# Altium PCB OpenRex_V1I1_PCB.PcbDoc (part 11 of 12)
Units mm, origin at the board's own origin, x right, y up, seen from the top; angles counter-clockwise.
Board outline 70 x 95 mm, 10 copper layers (L1, L2, L3, L4 (PWR), L5 (PWR), L6 (PWR), L7 (PWR), L8, L9, L10), stack 1.632 mm thick; 1080 components, 708 nets, 3831 pads, 2373 vias.
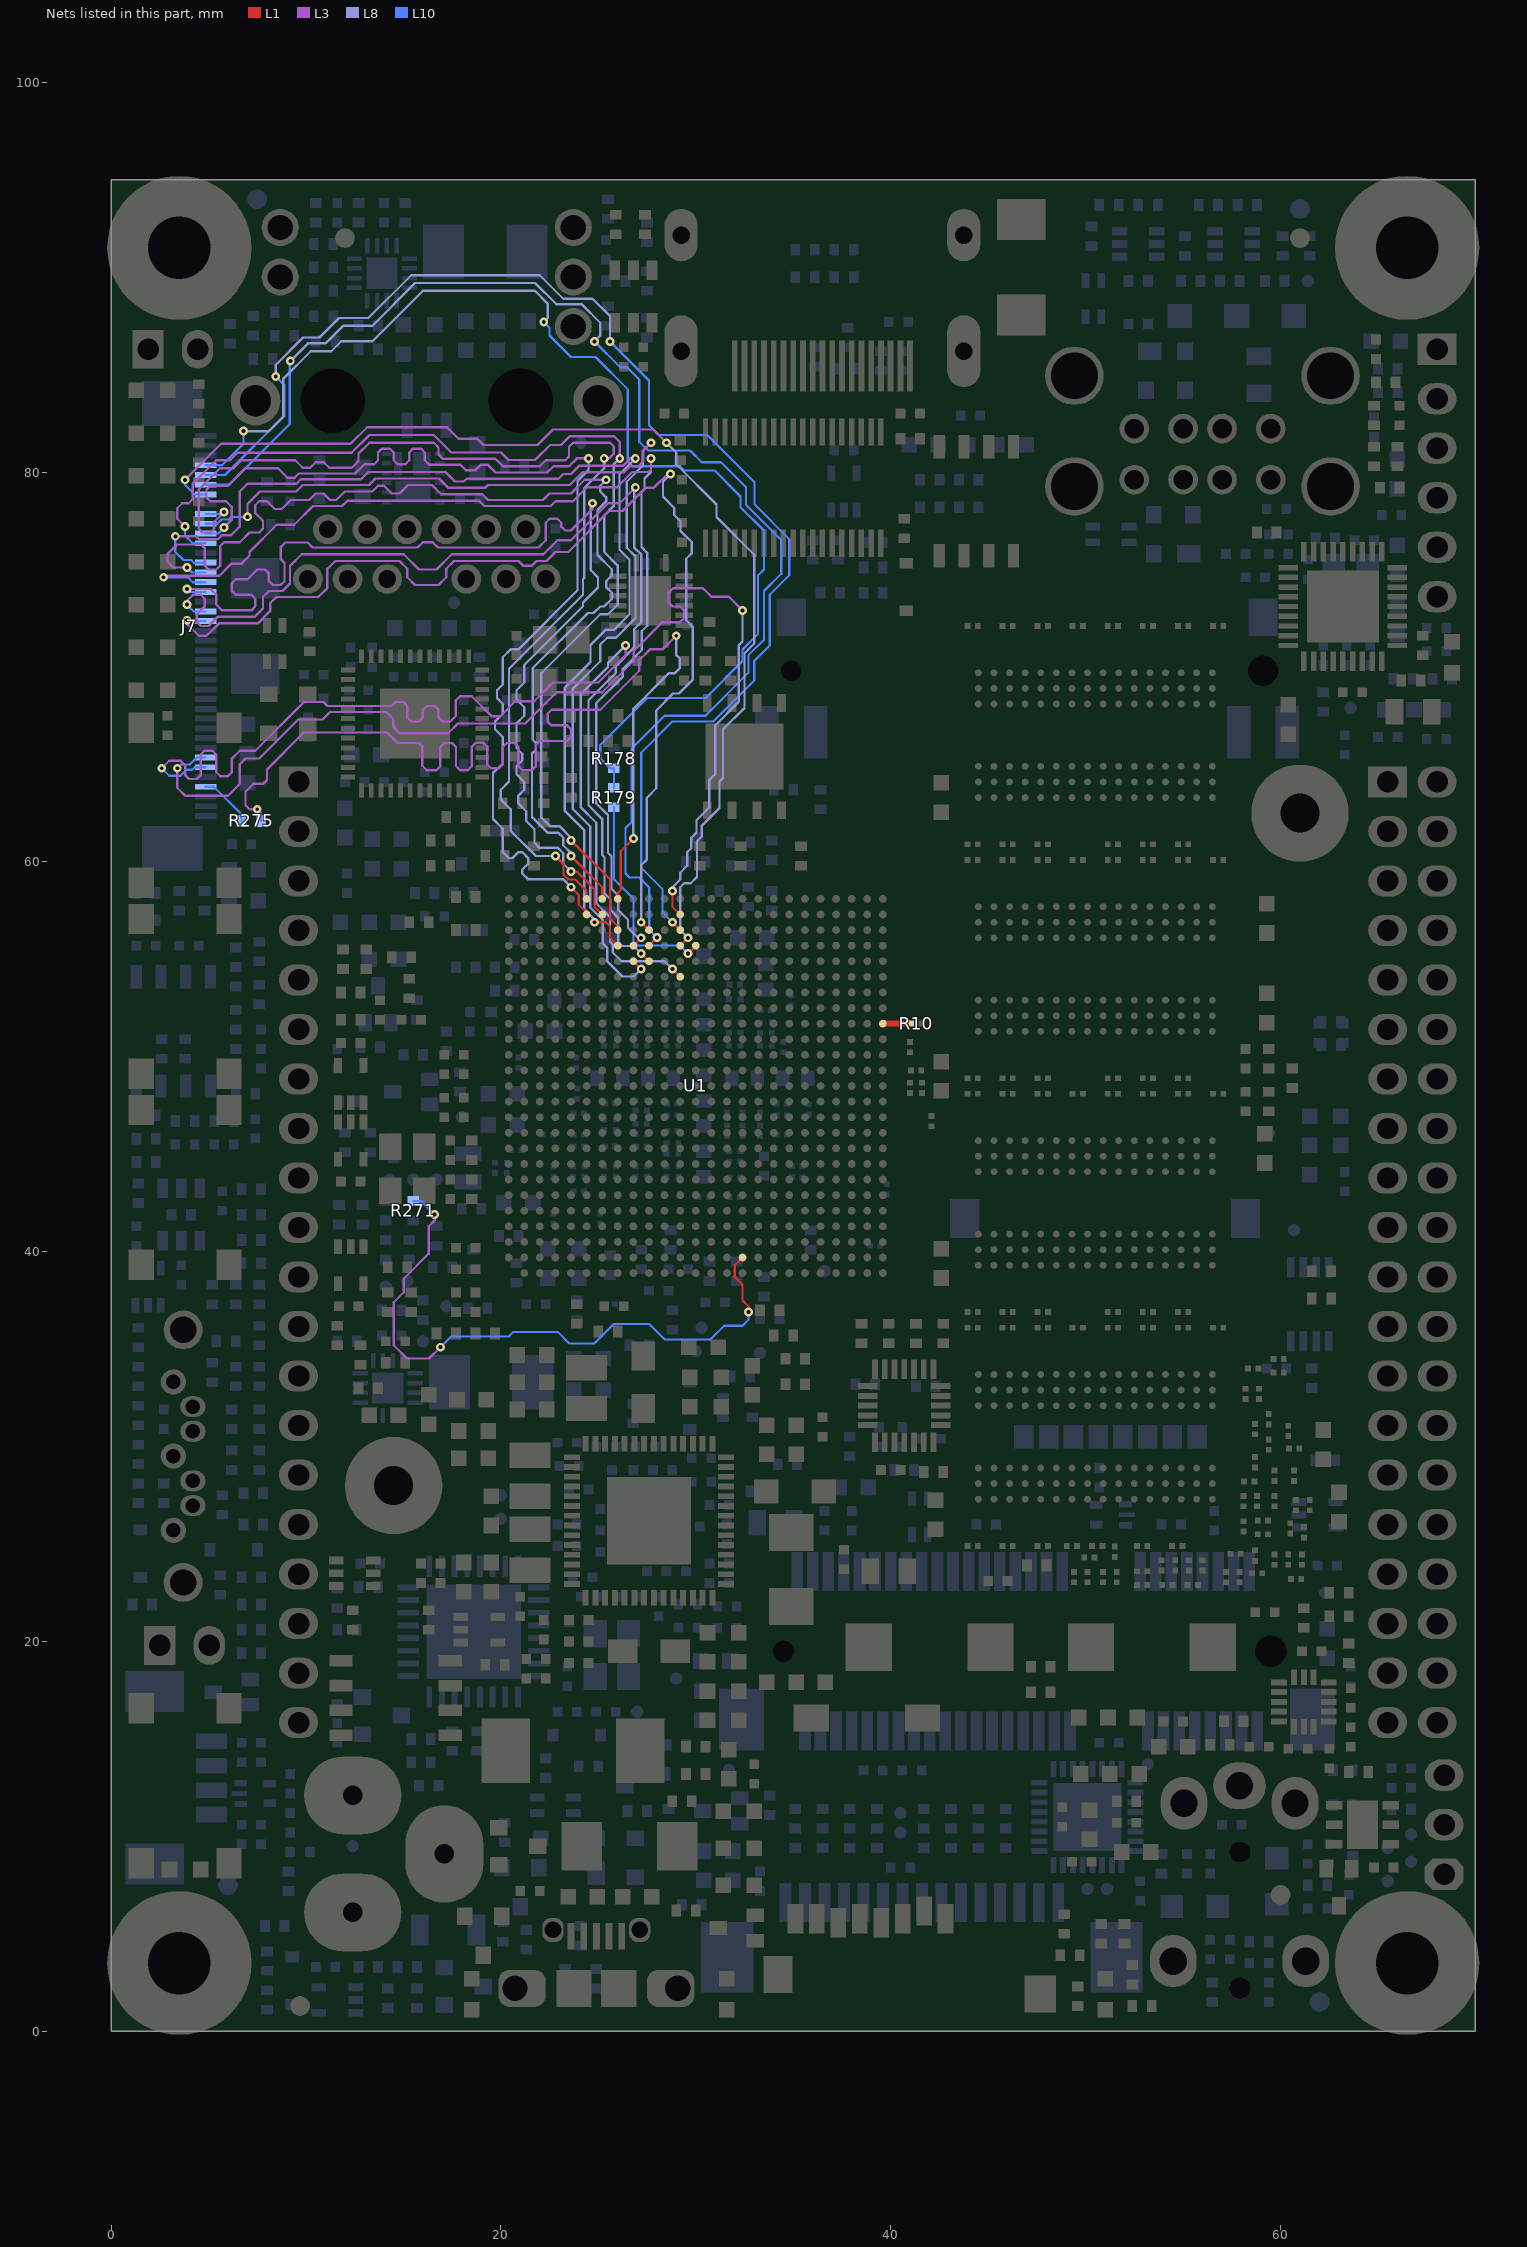
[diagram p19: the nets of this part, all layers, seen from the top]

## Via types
v1: diameter 0.45, hole 0.2, L1 to L10, tented both sides, 2369 vias
v2: diameter 1, hole 0.5, L1 to L10, tented top, 4 vias

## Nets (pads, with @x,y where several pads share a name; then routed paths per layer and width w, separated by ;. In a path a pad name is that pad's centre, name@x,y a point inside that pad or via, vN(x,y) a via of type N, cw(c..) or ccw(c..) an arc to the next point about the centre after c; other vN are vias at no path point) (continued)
VID_IN_CSI1_D10: J7.21 U1.K23 | length 58.1
  L1 w0.114: v1(27.2,56.9) U1.K23@27.6,56.5
  L3 w0.12: v1(3.9,72.4) 3.9,72.2 4.5,71.6 4.9,71.6 5.535,72.235 7.535,72.235 8.163,72.863 8.163,73.263 8.491,73.591 10.635,73.591 11.1,74.056 11.1,75.035 11.5,75.435 14.8,75.435 15.2,75.035 15.2,74.6 15.6,74.2 16.8,74.2 17.2,74.6 17.2,75.035 17.6,75.435 20.9,75.435 21.135,75.2 21.6,75.2 21.835,75.435 22.335,75.435 22.8,75.9 23.456,75.9 25.556,78 26.244,78 27.444,79.2 27.86,79.2 28.56,79.9 v1(28.7,79.9)
  L8 w0.12: v1(27.2,56.9) 27.2,59.828 27.491,60.119 27.491,63.291 27.972,63.772 27.972,67.769 28.838,68.635 29.135,68.635 29.837,69.337 29.837,72.063 29.509,72.391 29.509,75.553 29.8,75.844 29.8,76.4 29.22,76.98 29.22,77.48 28.9,77.8 28.9,78.156 28.315,78.741 28.315,79.515 v1(28.7,79.9)
  L10 w0.114: v1(3.9,72.4) 3.95,72.35 J7.21@4.85,72.35
VID_IN_CSI1_D11: J7.22 U1.K21 | length 58.1
  L1 w0.114: v1(27.2,55.3) U1.K21@27.6,54.9
  L3 w0.12: v1(3.9,73.2) 3.9,73.4 4.2,73.7 4.6,73.7 4.8,73.5 4.8,73.1 4.4,72.7 4.4,72.3 4.6,72.1 5,72.1 5.467,72.568 7.363,72.568 7.8,73.004 7.8,73.6 8.1,73.9 8.796,73.9 9.182,74.286 9.182,75.182 9.783,75.783 15.017,75.783 15.8,75 16.7,75 17.483,75.783 22.183,75.783 22.9,76.5 23.6,76.5 25.5,78.4 26.1,78.4 v1(26.9,79.2)
  L8 w0.12: v1(26.9,79.2) 26.838,79.138 26.838,76.133 27.21,75.762 27.21,72.31 26.838,71.938 26.838,70.994 25.9,70.056 25.9,69.7 24.495,68.295 24.495,62.905 25.195,62.205 25.195,60.364 25.32,60.239 25.32,58.38 25.61,58.09 25.61,57.55 26.015,57.145 26.015,55.885 26.215,55.685 26.815,55.685 v1(27.2,55.3)
  L10 w0.114: v1(3.9,73.2) 4.25,72.85 J7.22@4.85,72.85
VID_IN_CSI1_D12: J7.24 U1.G24 | length 58
  L1 w0.114: v1(23.6,59.5) 23.9,59.5 24.8,58.6 24.8,57.7 U1.G24@25.2,57.3
  L3 w0.12: v1(3.9,74) 5.1,74 5.4,73.7 5.4,73.2 5.7,72.9 7.2,72.9 7.4,73.1 7.4,73.5 7.2,73.7 6.4,73.7 6.2,73.9 6.2,74.3 6.4,74.5 7,74.5 7.5,75 7.9,75 8.1,74.8 8.1,74.4 8.3,74.2 8.7,74.2 8.9,74.4 8.9,75.326 8.715,75.511 8.715,76.159 8.941,76.385 10.088,76.385 10.342,76.131 15.731,76.131 16,76.4 16.5,76.4 16.769,76.131 21.931,76.131 22.3,76.5 22.3,77.4 22.5,77.6 22.9,77.6 23.1,77.4 23.1,77.2 23.3,77 23.6,77 24.7,78.1 v1(24.7,78.4)
  L8 w0.12: v1(23.6,59.5) 23.2,59.9 23.2,60.444 22.929,60.715 21.985,60.715 21.725,60.975 21.725,61.675 21.3,62.1 21.3,62.6 20.9,63 20.9,63.4 21.2,63.7 21.2,64.1 20.8,64.5 20.8,64.9 21.1,65.2 21.1,65.55 20.8,65.85 20.8,67.1 21.2,67.5 21.2,67.935 20.8,68.335 20.8,68.8 21.2,69.2 21.2,70.1 24.215,73.115 24.215,73.309 24.985,74.079 24.985,74.594 24.617,74.962 24.617,78.317 v1(24.7,78.4)
  L10 w0.114: v1(3.9,74) 4.05,73.85 J7.24@4.85,73.85
VID_IN_CSI1_D13: J7.25 U1.J22 | length 58.1
  L1 w0.114: U1.J22@26.8,55.7 v1(27.2,56.1)
  L3 w0.12: v1(2.7,74.6) 2.78,74.68 5.56,74.68 6.18,75.3 6.7,75.3 7.1,75.7 7.1,75.9 8.5,77.3 9.4,77.3 10.355,78.255 11.855,78.255 12.129,78.529 18.871,78.529 19.145,78.255 22.555,78.255 22.8,78.5 23.7,78.5 24.415,79.215 25.951,79.215 26.736,80 27.6,80 27.7,80.1 v1(27.7,80.7)
  L8 w0.12: v1(27.2,56.1) 27.045,56.1 26.525,56.62 26.525,57.031 26.015,57.541 26.015,58.285 25.68,58.62 25.68,60.29 25.5,60.47 25.5,62.4 24.899,63.001 24.899,68.143 26.26,69.504 26.26,69.9 27.233,70.873 27.233,71.833 27.515,72.115 27.515,72.599 27.515,75.853 27.215,76.153 27.215,78.959 27.372,79.117 27.372,79.668 27.7,79.996 v1(27.7,80.7)
  L10 w0.114: v1(2.7,74.6) 3.944,74.6 4.194,74.35 J7.25@4.85,74.35
VID_IN_CSI1_D14: J7.26 U1.G25 | length 58.1
  L1 w0.114: v1(23.6,60.3) 25.2,58.7 U1.G25@25.2,58.1
  L3 w0.12: v1(3.9,75.1) 3.2,75.1 2.9,75.4 2.9,75.8 3.385,76.285 4.615,76.285 4.8,76.1 4.8,75.2 5,75 5.4,75 5.6,75.2 5.6,76.206 5.603,76.208 ; 5.606,76.206 5.8,76.4 6.6,76.4 7.1,76.9 7.6,76.9 7.8,77.1 7.8,77.5 7.4,77.9 7.4,78.3 7.6,78.5 8,78.5 8.4,78.1 8.756,78.1 9.221,78.565 10.165,78.565 10.5,78.9 10.9,78.9 11.235,78.565 11.559,78.565 11.994,79 13.4,79 13.7,79.3 14,79.3 14.4,78.9 14.8,78.9 15.235,79.335 16.465,79.335 16.942,78.858 19.042,78.858 19.335,78.565 22.165,78.565 22.5,78.9 23.6,78.9 24.3,79.6 v1(25.4,79.6)
  L8 w0.12: v1(23.6,60.3) 23.6,60.455 23.2,60.855 23.2,61.244 22.959,61.485 22.415,61.485 21.6,62.3 21.6,65.556 21.8,65.756 21.8,66.1 21.638,66.262 21.638,69.938 24.465,72.765 24.759,72.765 25.094,73.1 25.294,73.1 25.685,73.491 25.685,73.815 25.4,74.1 25.4,74.4 25.685,74.685 25.685,75.015 24.959,75.741 24.959,78.048 25.4,78.489 25.4,78.7 25.1,79 25.1,79.3 v1(25.4,79.6)
  L10 w0.114: v1(3.9,75.1) 4.15,74.85 J7.26@4.85,74.85
VID_IN_CSI1_D15: J7.27 U1.H22 | length 58.1
  L1 w0.114: v1(24.8,56.9) 25.4,56.9 25.6,56.7 25.6,56.1 U1.H22@26,55.7
  L3 w0.12: v1(3.3,76.7) 4.365,76.7 4.5,76.565 5.5,76.565 5.7,76.765 6.165,76.765 6.6,77.2 6.6,79 7,79.4 9.51,79.4 9.738,79.628 12.828,79.628 13.2,80 17.156,80 17.641,79.515 18.1,79.515 18.24,79.655 22.955,79.655 23.2,79.9 23.6,79.9 24.015,80.315 26.259,80.315 26.644,80.7 v1(26.9,80.7)
  L8 w0.12: v1(24.8,56.9) 24.8,57.048 24.287,57.562 24.287,61.613 23.285,62.615 23.285,68.941 24.6,70.256 24.6,71.132 25.368,71.9 25.8,71.9 26.6,72.7 26.6,75.5 26.085,76.015 26.085,79.885 v1(26.9,80.7)
  L10 w0.114: v1(3.3,76.7) 3.3,75.9 3.715,75.485 4.115,75.485 4.25,75.35 J7.27@4.85,75.35
VID_IN_CSI1_D16: J7.29 U1.H23 | length 58.1
  L1 w0.114: v1(23.6,61.1) 25.6,59.1 25.6,57.096 26,56.696 U1.H23@26,56.5
  L3 w0.12: v1(3.8,77.2) 3.4,77.6 3.4,78.144 3.656,78.4 3.985,78.4 4.185,78.6 4.185,79.385 5.4,80.6 6.1,80.6 6.485,80.985 12.345,80.985 13.26,81.9 16.556,81.9 17.456,81 20,81 20.385,80.615 20.9,80.615 21.759,80.615 22.529,81.385 23.085,81.385 23.543,81.843 25.791,81.843 26.1,81.533 v1(26.1,80.7)
  L8 w0.12: v1(23.6,61.1) 23.6,61.24 23.005,61.835 22.525,61.835 22.077,62.283 22.077,65.636 22.08,65.64 22.08,66.216 22.077,66.219 22.077,69.673 25.104,72.7 25.5,72.7 25.99,73.19 25.99,75.21 25.3,75.9 25.3,77.768 25.785,78.253 25.785,80.385 v1(26.1,80.7)
  L10 w0.114: v1(3.8,77.2) 3.8,76.744 4.194,76.35 J7.29@4.85,76.35
VID_IN_CSI1_D17: J7.30 U1.F24 | length 58.1
  L1 w0.114: v1(23.6,58.7) 24,58.3 24,57.8 24.4,57.4 U1.F24@24.4,57.3
  L3 w0.12: v1(5.8,77.15) 6.185,77.535 6.185,78.215 5.9,78.5 5.1,78.5 4.9,78.7 4.9,79.1 5.1,79.3 6,79.3 6.9,80.2 8.556,80.2 9.041,79.715 9.429,79.715 9.635,79.922 12.522,79.922 13,80.4 13.5,80.4 13.7,80.6 13.7,81 13.9,81.2 14.3,81.2 14.5,81 14.5,80.6 14.7,80.4 15.1,80.4 15.3,80.6 15.3,81 15.5,81.2 15.9,81.2 16.1,81 16.1,80.6 16.32,80.38 17.92,80.38 18.2,80.1 18.7,80.1 18.98,80.38 19.32,80.38 19.725,79.975 22.375,79.975 22.7,80.3 23.5,80.3 23.9,80.7 v1(24.5,80.7)
  L8 w0.12: v1(23.6,58.7) 23.185,59.115 21.385,59.115 21.1,59.4 21.1,59.6 21.4,59.9 21.4,60.2 21.1,60.5 20.9,60.5 20.6,60.2 20.4,60.2 20.1,60.5 20.1,61.7 19.6,62.2 19.6,64.556 20.1,65.056 20.1,66.4 19.7,66.8 19.7,67.2 20.1,67.6 20.1,68.1 19.8,68.4 19.8,68.8 20.1,69.1 20.1,70.5 20.5,70.9 20.9,70.9 23.935,73.935 23.935,79.535 24.5,80.1 v1(24.5,80.7)
  L10 w0.114: J7.30@4.85,76.85 5.5,76.85 v1(5.8,77.15)
VID_IN_CSI1_D18: J7.31 U1.J21 | length 58.1
  L1 w0.114: U1.J21@26.8,54.9 v1(27.2,54.5)
  L3 w0.12: v1(7,77.7) 7,78.36 7.64,79 9.506,79 9.841,79.335 13.235,79.335 13.567,79.667 16.833,79.667 17.314,79.186 19.192,79.186 19.341,79.335 23.535,79.335 24.185,79.985 26.325,79.985 26.64,80.3 27.044,80.3 27.3,80.556 27.3,81.1 v1(27.7,81.5)
  L8 w0.12: 23.688,68.896 23.688,62.712 24.588,61.812 24.588,57.656 25.22,57.024 25.22,55.82 25.465,55.575 25.465,54.891 26.241,54.115 26.815,54.115 v1(27.2,54.5) ; 23.7,68.896 25.1,70.296 25.1,71.144 25.456,71.5 25.9,71.5 26.905,72.505 26.905,75.671 26.462,76.114 26.462,79.506 27.285,80.329 27.285,81.085 v1(27.7,81.5)
  L10 w0.114: J7.31@4.85,77.35 5.456,77.35 5.671,77.565 6.035,77.565 6.17,77.7 v1(7,77.7)
VID_IN_CSI1_D19: J7.32 U1.F25 | length 58
  L1 w0.114: v1(22.8,60.3) 23.215,59.885 23.215,59.341 23.456,59.1 23.8,59.1 24.4,58.5 U1.F25@24.4,58.1
  L3 w0.12: v1(5.8,77.95) 5.3,77.45 5.3,77.1 5.1,76.9 4.7,76.9 4.5,77.1 4.5,79.1 5.6,80.2 6.3,80.2 6.7,80.6 9.456,80.6 9.841,80.215 10.215,80.215 10.5,80.5 10.915,80.5 11.2,80.215 12.359,80.215 12.7,80.556 12.7,80.944 13.256,81.5 16.56,81.5 16.8,81.26 16.8,80.9 17.01,80.69 19.71,80.69 20.105,80.295 21.995,80.295 22.3,80.6 23.3,80.6 23.5,80.8 23.5,81.3 23.7,81.5 25.6,81.5 25.8,81.3 25.8,80.944 25.556,80.7 v1(25.3,80.7)
  L8 w0.12: v1(22.8,60.3) 21.8,60.3 20.5,61.6 20.5,62.7 20,63.2 20,63.7 20.415,64.115 20.415,69.905 24.215,73.705 24.215,74.509 24.276,74.571 24.276,79.176 25.3,80.2 v1(25.3,80.7)
  L10 w0.114: J7.32@4.85,77.85 5.7,77.85 v1(5.8,77.95)
VID_IN_CSI1_DE: J7.34 U1.M22 | length 58.1
  L1 w0.114: U1.M22@29.2,55.7 v1(29.6,56.1)
  L3 w0.12: v1(3.8,79.6) 5.647,81.447 12.289,81.447 13.142,82.3 17.244,82.3 17.844,81.7 18.8,81.7 19.115,81.385 21.879,81.385 22.679,82.185 27.815,82.185 v1(28.5,81.5)
  L8 w0.12: v1(28.5,81.5) 29,81 29,80.4 31.065,78.335 31.065,77.691 33,75.756 33,71.2 32.5,70.7 32.5,67.9 31.4,66.8 31.4,64.3 31.215,64.115 31.215,62.759 30.315,61.859 30.315,61.315 30.06,61.06 30.06,59.216 29.744,58.9 29.4,58.9 29.2,58.7 29.2,56.5 v1(29.6,56.1)
  L10 w0.114: v1(3.8,79.6) 3.8,79.344 4.294,78.85 J7.34@4.85,78.85
VID_IN_CSI1_HSYNC: J7.6 U1.M20 | length 58.2
  L1 w0.114: v1(28.8,54.5) U1.M20@29.2,54.1
  L3 w0.12: v1(2.6,64.8) 2.985,65.185 3.571,65.185 3.8,64.956 3.8,64.45 4,64.25 4.4,64.25 4.6,64.45 4.6,65.5 4.8,65.7 5.2,65.7 5.4,65.5 5.4,64.6 5.6,64.4 6,64.4 6.2,64.6 6.2,65.3 6.6,65.7 7.4,65.7 9.9,68.2 10.9,68.2 11.1,68 14.4,68 14.6,68.2 15,68.2 15.2,68 15.2,67.4 15.4,67.2 15.8,67.2 16,67.4 16,67.8 16.2,68 16.6,68 16.8,67.8 16.8,67.4 17,67.2 17.4,67.2 17.685,67.485 17.685,68.285 17.9,68.5 18.504,68.5 19.539,67.465 19.965,67.465 20.735,68.235 21.712,68.235 22.677,69.2 25,69.2 26.4,70.6 v1(26.4,71.1)
  L8 w0.12: v1(26.4,71.1) 25.5,70.2 25.5,70 24.092,68.592 24.092,62.808 24.89,62.01 24.89,57.874 25.6,57.164 25.6,55.904 25.745,55.759 25.745,55.355 26.2,54.9 28.4,54.9 v1(28.8,54.5)
  L10 w0.114: v1(2.6,64.8) 2.985,64.415 3.559,64.415 3.864,64.72 4.16,64.72 4.29,64.85 J7.6@4.85,64.85
VID_IN_CSI1_INT: J7.35 U1.K22 | length 71
  L1 w0.114: U1.K22@27.615,55.715 v1(28.015,56.115)
  L8 w0.12: v1(9.2,85.7) 10.1,86.6 11,86.6 11.9,87.5 13.4,87.5 15.6,89.7 21.756,89.7 22.842,88.614 24.144,88.614 25.1,87.659 25.1,87 v1(24.8,86.7)
  L10 w0.114: J7.35@4.85,79.35 6.05,79.35 9.164,82.464 9.164,85.664 v1(9.2,85.7) ; v1(24.8,86.7) 26.128,85.372 26.472,85.372 27.1,84.744 27.1,81.556 27.556,81.1 29.7,81.1 30.3,80.5 31.3,80.5 32.58,79.22 32.58,78.32 34.385,76.515 34.385,74.785 33.5,73.9 33.5,71.4 32.7,70.6 32.7,69.7 30.5,67.5 28.4,67.5 26.7,65.8 26.7,62.036 26.4,61.736 26.4,59.4 26.6,59.2 27.1,59.2 27.615,58.685 27.615,56.515 v1(28.015,56.115)
VID_IN_CSI1_INT2: J7.36 U1.M23 | length 70
  L1 w0.114: v1(28.8,56.9) U1.M23@29.2,56.5
  L8 w0.12: v1(8.45,84.9) 8.45,85.494 9.856,86.9 10.7,86.9 11.7,87.9 13.2,87.9 15.4,90.1 22,90.1 23.206,88.894 24.706,88.894 25.6,88 v1(25.6,86.7)
  L10 w0.114: J7.36@4.85,79.85 5.85,79.85 8.884,82.884 8.884,84.466 v1(8.45,84.9) ; v1(25.6,86.7) 27.6,84.7 27.6,82.4 28.1,81.9 30.596,81.9 33.015,79.481 33.015,78.341 34.8,76.556 34.8,74.7 33.8,73.7 33.8,71.1 33,70.3 33,69.3 30.9,67.2 28.8,67.2 27.2,65.6 27.2,59.7 28.3,58.6 28.3,57.4 v1(28.8,56.9)
VID_IN_CSI1_PIXCLK: R275.1 U1.H25 | length 55.7
  L1 w0.114: U1.H25@26,58.1 26,58.4 26.15,58.55 26.15,60.55 v1(26.8,61.2)
  L3 w0.12: v1(7.5,62.7) 7.1,62.7 6.9,62.9 6.9,63.6 7.3,64 7.8,64 8,64.2 8,64.744 9.891,66.635 14.165,66.635 14.7,66.1 15.8,66.1 15.965,65.935 15.965,64.935 16.2,64.7 16.7,64.7 16.895,64.895 16.895,65.895 17.1,66.1 17.5,66.1 17.7,65.9 17.7,64.895 ; 17.7,64.9 17.9,64.7 18.3,64.7 18.5,64.9 18.5,65.9 18.705,66.105 19.105,66.105 19.3,65.91 19.3,65 19.5,64.8 19.9,64.8 20.1,65 20.1,65.9 20.3,66.1 20.7,66.1 20.9,65.9 20.9,64.9 21.1,64.7 21.6,64.7 21.785,64.885 21.785,65.985 22,66.2 23.4,66.2 23.6,66.4 23.6,66.8 23.4,67 22.6,67 22.4,67.2 22.4,67.6 22.6,67.8 25.1,67.8 27.1,69.8 27.1,70.344 27.656,70.9 28.3,70.9 v1(29,71.6)
  L8 w0.12: v1(26.8,61.2) 26.8,67.856 28.629,69.685 28.929,69.685 29.185,69.941 29.185,70.423 29,70.608 v1(29,71.6)
  L10 w0.114: v1(7.5,62.7) 7.7,62.5 R275.1@7.7,62.1
VID_IN_CSI1_PIXCLK_R: J7.4 R275.2 | length 2.8
  L10 w0.114: J7.4@4.85,63.85 5.276,63.85 6.7,62.426 R275.2@6.7,62.1
VID_IN_CSI1_RSTN: J7.37 R178.1 R179.1 | length 61.4
  L8 w0.12: v1(6.8,82.1) 8.1,82.1 8.842,82.842 8.842,84.797 10.244,86.2 11.3,86.2 11.815,86.715 13.415,86.715 16,89.3 21.744,89.3 22.4,88.644 22.4,87.9 v1(22.2,87.7)
  L10 w0.114: J7.37@4.85,80.35 5.694,80.35 6.8,81.456 v1(6.8,82.1) ; v1(22.2,87.7) 22.5,87.4 22.5,87 23.6,85.9 24.856,85.9 26.515,84.241 26.515,80.541 26.756,80.3 29.2,80.3 29.415,80.085 30.959,80.085 32.3,78.744 32.3,78.2 33.5,77 33.5,75 33.2,74.7 33.2,71.7 32.4,70.9 32.4,70.3 30.5,68.4 27.5,68.4 25.1,66 25.1,65.3 25.6,64.8 R178.1@25.8,64.8 R179.1@25.8,63.8
VID_IN_CSI1_RSTN_R: R179.2 U1.N22 | length 10.9
  L1 w0.114: v1(29.6,55.3) U1.N22@30,55.7
  L10 w0.114: R179.2@25.8,62.8 25.8,59.1 26.8,58.1 26.8,55.9 26.985,55.715 29.185,55.715 v1(29.6,55.3)
VID_IN_CSI1_VSYNC: J7.7 U1.M24 | length 58.1
  L1 w0.114: v1(28.8,58.5) 28.8,57.7 U1.M24@29.2,57.3
  L3 w0.12: v1(3.4,64.8) 3.4,63.8 3.815,63.385 5.985,63.385 6.6,64 6.6,65 6.9,65.3 7.6,65.3 9.6,67.3 10.844,67.3 11.229,67.685 14.115,67.685 14.485,67.315 14.485,66.915 14.8,66.6 17.3,66.6 17.8,67.1 21.256,67.1 22.856,68.7 25.2,68.7 26.82,70.32 26.82,70.82 28.3,72.3 29.2,72.3 29.4,72.5 29.4,72.9 29.2,73.1 28.8,73.1 28.6,73.3 28.6,73.8 28.835,74.035 30.365,74.035 30.8,73.6 31.7,73.6 v1(32.4,72.9)
  L8 w0.12: v1(28.8,58.5) 28.8,58.7 29.2,59.1 29.2,59.444 29.556,59.8 29.556,60.491 29.765,60.7 29.765,61.23 30.035,61.5 30.035,62.135 30.7,62.8 30.7,64.2 31,64.5 31,67 32.2,68.2 32.2,71.1 32.4,71.3 v1(32.4,72.9)
  L10 w0.114: v1(3.4,64.8) 3.6,65 4.044,65 4.394,65.35 J7.7@4.85,65.35
WD_OUT: R271.1 U1.T2 | length 33.1
  L1 w0.114: U1.T2@32.4,39.7 32,39.3 32,38.7 32.4,38.3 32.4,37.5 32.7,37.2 v1(32.7,36.9)
  L3 w0.12: v1(16.6,41.9) 16.6,41.6 16.3,41.3 16.3,39.9 15.015,38.615 15.015,37.915 14.5,37.4 14.5,35.2 15.185,34.515 16.315,34.515 v1(16.9,35.1)
  L10 w0.114: R271.1@15.5,42.6 15.9,42.6 v1(16.6,41.9) ; v1(16.9,35.1) 17.45,35.65 20.406,35.65 20.641,35.885 22.915,35.885 23.515,35.285 24.785,35.285 25.785,36.285 27.615,36.285 28.4,35.5 30.756,35.5 31.456,36.2 32.4,36.2 32.7,36.5 v1(32.7,36.9)
ZQPAD: R10.1 U1.AE17 | length 1.4
  L1 w0.3: U1.AE17@39.6,51.7 R10.1@41.035,51.7
pads on no net: FID1.1 FID2.1 FID3.1 FID4.1 FID5.1 FID6.1 FID7.1 FID8.1 J6. J14.5 J14.7 J15.3 J15.5 J15.7 J15.45 J15.47 J15.55 J15.56 J16.7 J16.8 U1.A9 U1.A10 U1.A11 U1.AA1 U1.AA2 U1.AA3 U1.AA4 U1.AA11 U1.AB1 U1.AB2 U1.AB17 U1.AD17 U1.B9 U1.B10 U1.B11 U1.B20 U1.C5 U1.C8 U1.C16 U1.C19 U1.C20 U1.D5 U1.D16 U1.D18 U1.D19 U1.D20 U1.E1 U1.E2 U1.E13 U1.E16 U1.E18 U1.E25 U1.F1 U1.F2 U1.F13 U1.F15 U1.F18 U1.G1 U1.G2 U1.G4 U1.H1 U1.H2 U1.H3 U1.H4 U1.H24 U1.J19 U1.J20 U1.J23 U1.J24 U1.K20 U1.L1 U1.L3 U1.L4 U1.L6 U1.M2 U1.M4 U1.M5 U1.M6 U1.N5 U1.N6 U1.N19 U1.N20 U1.N21 U1.N23 U1.P4 U1.P5 U1.P6 U1.P20 U1.R3 U1.R5 U1.R20 U1.R21 U1.R23 U1.T20 U1.T23 U1.U20 U1.U22 U1.V24 U1.W6 U1.W20 U1.W21 U1.W23 U1.Y1 U1.Y2 U1.Y3 U1.Y4 U2.J1 U2.J9 U2.L1 U3.J1 U3.J9 U3.L1 U4.J1 U4.J9 U4.L1 U5.J1 U5.J9 U5.L1 U7.43 U9.33 U13.18 U13.20 U14.8 U14.9 U14.11 U14.12 U14.17 U14.18 U14.19 U14.22 U14.28 U26.3 U26.4 U29.1 U33.1

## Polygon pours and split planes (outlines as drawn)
+VIN_5V on L6 (PWR) "L6" (solid, remove dead copper, pour order 335): 47 vertices, not listed, extent 1,1 69,94
+V_INPUT on L6 (PWR) "L6" (solid, remove dead copper, pour order 334): 1,1 24,1 24,7.1 19.9,11.2 1,11.2
+PCIE_VP on L6 (PWR) "L6" (solid, remove dead copper, pour order 321): 25.3,43.6 25.6,43.6 26.2,43 26.2,41.4 24.3,39.5 24.3,37 20.6,37 20.6,40.8 22.4,40.8 24,42.4 24.8,42.4 25.3,42.9
+SATA_VP on L6 (PWR) "L6" (solid, remove dead copper, pour order 318): 24.7,37 25.8,37 27.8,39 27.8,44.4 26.2,46 26.2,47.2 25,48.4 24.2,48.4 24.2,44.8 25,44 25.8,44 26.6,43.2 26.6,41.2 24.7,39.3
+PCIE_VPH on L6 (PWR) "L6" (solid, remove dead copper, pour order 322): 20.6,41.2 22.2,41.2 23.8,42.8 24.6,42.8 24.9,43.1 24.9,43.6 23.7,44.8 21.6,44.8 20.6,43.8
+1V375_CORE on L6 (PWR) "L6" (solid, remove dead copper, pour order 323): 46 vertices, not listed, extent 21.8,30.219 60.4,66
+3V3_HDR_J2 on L6 (PWR) "L6" (solid, remove dead copper, pour order 324): 69,66 60.8,66 60.8,62.4 56.2,57.8 56.2,57.6 56.2,36.4 69,36.4
+2V5_ETH_DVDDH on L6 (PWR) "L6" (solid, remove dead copper, pour order 325): 28 vertices, not listed, extent 9.4,54 24.6,70.8
+3V3_ETH_AVDDH on L6 (PWR) "L6" (solid, remove dead copper, pour order 326): 12.4,70.6 12.4,71 14,72.6 16,72.6 17.2,73.8 22.6,73.8 22.6,69 19.4,69 18.8,69.6 18.2,70.2 12.8,70.2
+5V on L6 (PWR) "L6" (solid, remove dead copper, pour order 327): 80 vertices, not listed, extent 7.2,17.4 65,82.6
+1V5_DDR on L6 (PWR) "L6" (solid, remove dead copper, pour order 328): 30.6,18 31.6,18 31.6,19.9 29.9,21.6 28.8,21.6 28.8,21 30.4,19.4 30.4,18.2
+1V8_AUDIO on L6 (PWR) "L6" (solid, remove dead copper, pour order 329): 31 vertices, not listed, extent 23,14.6 53,24.4
+0V75_DDR_VTT on L6 (PWR) "L6" (solid, remove dead copper, pour order 330): 47 vertices, not listed, extent 15.8,9 69,36
+MPCIE_SIM_VPP on L6 (PWR) "L6" (solid, remove dead copper, pour order 331): 48.4,24.8 52.2,24.8 52.8,25.4 52.8,26 52.8,30.6 48.4,30.6
+3V3_COMP on L6 (PWR) "L6" (solid, remove dead copper, pour order 333): 63,19 69,19 69,11.8 62.2,11.8 57.8,11.8 57.8,13.8 63,19
+VDDUSB on L5 (PWR) "L5" (solid, remove dead copper, pour order 336): 24.4,44.6 23.4,43.6 19.8,43.6 19.8,44.8 20.6,45.6 23.6,45.6 24.4,44.8
+PCIE_VPTX on L5 (PWR) "L5" (solid, remove dead copper, pour order 337): 19.8,43.2 23.6,43.2 24.6,44.2 25,44.2 25.2,44 25.4,44 25.4,43.8 25.4,43.2 23,40.8 23,40.2 22.4,40.2 19.8,40.2
+2V5_VDDHIGH_VPH on L5 (PWR) "L5" (solid, remove dead copper, pour order 339): 18 vertices, not listed, extent 23.4,40.2 29.6,47.2
+SATA_VPH on L5 (PWR) "L5" (solid, remove dead copper, pour order 340): 25.2,47.8 24,49 23.2,49.8 21.6,49.8 17.8,49.8 17.8,52 25.2,52 26.2,51 26.2,50.4 26.2,47.8
+NVCC_RGMII on L5 (PWR) "L5" (solid, remove dead copper, pour order 341): 24.6,52.4 25,52.4 25,53 24.6,53.4 24.6,58.6 16.4,58.6 16.4,52.4
+VDDPU on L5 (PWR) "L5" (solid, remove dead copper, pour order 342): 26.6,47.6 29,47.6 29.4,48 29.4,51 29.4,51.2 34.2,51.2 34.2,58.6 25,58.6 25,53.6 25.4,53.2 25.4,52.4 26.6,51.2 26.6,47.8
+1V1_VDDSOC_CAP on L5 (PWR) "L5" (solid, remove dead copper, pour order 343): 24 vertices, not listed, extent 23,36 34.2,50.8
+0V75_DDR_VTT on L5 (PWR) "L5" (solid, remove dead copper, pour order 344): 22.9,27 20.6,27 18.6,29 18.6,31.8 19.8,31.8 20.6,31.8 20.6,31 20.6,30.2 20.6,29.8 22.9,27.5
+1V375_SOC on L5 (PWR) "L5" (solid, remove dead copper, pour order 346): 19.2,32.2 23.2,32.2 23.2,33.4 23,33.6 17.4,33.6 15.8,35.2 15.6,35.2 15.4,35 15.4,34.2 17.2,32.4 17.4,32.2
+1V2_PMIC on L5 (PWR) "L5" (solid, remove dead copper, pour order 347): 28 vertices, not listed, extent 22.6,27.1 43.4,83.2
+5V on L5 (PWR) "L5" (solid, remove dead copper, pour order 349): 32.8,23 35.2,23 37,23 37,24.8 37,30.6 36,30.6 35.2,29.8 35.2,28.4 33.4,26.6 32.4,26.6 32.4,23.4
+3V0_ALWAYS on L5 (PWR) "L5" (solid, remove dead copper, pour order 350): 92 vertices, not listed, extent 1,21 34.2,52
SPLIT on L5 (PWR) "L5" (solid, remove dead copper, pour order 352): 2.6,47.4 2.6,45 7.4,45 7.4,46.4 7.4,47.4 6.6,48.2 3.6,48.2 3.4,48.2
+VCC_CAN on L5 (PWR) "L5" (solid, remove dead copper, pour order 353): 19 vertices, not listed, extent 1,42.8 13.4,56.2
+1V2_ETH on L5 (PWR) "L5" (solid, remove dead copper, pour order 355): 19 vertices, not listed, extent 10.8,59 34.2,82.4
+1V2_ETH_DVDDL on L5 (PWR) "L5" (solid, remove dead copper, pour order 356): 9.4,62.4 17.8,62.4 18.2,62.8 20,64.6 20,65.4 20,66.2 19,67.2 16.4,69.8 16.4,71.2 13,71.2 8.8,67 8.8,63
+5V_HDMI_CON on L5 (PWR) "L5" (solid, remove dead copper, pour order 358): 30.2,81 31.8,79.4 37.2,79.4 39.8,79.4 39.8,82 43.1,85.3 43.1,87.8 38.4,87.8 36.6,87.8 31,82.2 30.2,82.2
+5V_USB_BOT on L5 (PWR) "L5" (solid, remove dead copper, pour order 359): 23 vertices, not listed, extent 40.2,75.8 60.2,89.8
+5V_USB_TOP on L5 (PWR) "L5" (solid, remove dead copper, pour order 360): 48.4,88 50.6,88 51.6,87 57.6,81 58.2,81 60.2,81 60.2,80.4 60.2,79.2 60.2,76 60.2,75.8 48.4,75.8
+3V3_HDR on L5 (PWR) "L5" (solid, remove dead copper, pour order 361): 44 vertices, not listed, extent 1,44.6 69,94
+MPCIE_SIM_PWR on L5 (PWR) "L6" (solid, remove dead copper, pour order 365): 51,22.4 51,23.8 52.4,25.2 55.6,25.2 56,24.8 56.2,24.6 56.2,22 55.8,22 55.4,22.4
+3V3_GYRO_IO on L5 (PWR) "L6" (solid, remove dead copper, pour order 366): 37.4,23 45.6,23 45.6,28.8 45.6,35.4 44,37 42,37 37.4,37
+3V0_VSNVS on L5 (PWR) "L6" (solid, remove dead copper, pour order 367): 60 vertices, not listed, extent 1,12.8 33.8,29.2
+3V3_COMP_IO on L5 (PWR) "L5" (solid, remove dead copper, pour order 369): 69,22.6 69,1 60.4,1 60.4,20.6 62.4,22.6 69,22.6
+1V5_DDR on L5 (PWR) "L5" (solid, remove dead copper, pour order 370): 31.2,18.2 31.6,18.6 33.8,18.6 33.8,14.4 34.4,13.8 35.2,13 35.2,10.4 34.4,9.6 33.2,9.6 31.2,11.6
+3V3_MCU on L5 (PWR) "L5" (solid, remove dead copper, pour order 371): 30 vertices, not listed, extent 1,1 60,25.4
GND on L1 "Power Plane" (solid, pour order 320): 21.6,17.9 21.6,19.6 21.1,20.1 20.7,20.1 20.6,20 20.6,19.8 20.7,19.7 20.7,19.4 20.7,18.2 21,17.9 21.1,17.8 21.6,17.8
+5V_USB_BOT on L1 "L10" (solid, remove dead copper, pour order 351): 42.8,81.3 42.8,83 42.6,83.2 42.3,83.2 42,82.9 42,82.1 42,81.5 42.2,81.3
GND on L1 "L1" (solid, pour order 417): 20 vertices, not listed, extent 30.591,51.5 33.4,52.7
GND on L1 "L10" (solid, remove dead copper, pour order 625): 41.9,25.3 42.9,25.3 43.2,25.6 43.2,26.4 42.8,26.4 42.6,26.2 41.9,26.2
+1V5_DDR on L1 "L10" (solid, remove dead copper, pour order 624): 41.9,26.8 42.8,26.8 43.5,27.5 43.5,27.6 42.9,28.2 42.7,28.2 42.4,28.2 41.9,27.7 41.9,26.8
FB_1V375 on L1 "L10" (solid, remove dead copper, pour order 623): 12.5,35.5 12.5,34.9 13.1,34.9 13.5,34.5 13.7,34.3 13.7,34.2 13.7,34.1 13.8,34 14.4,34 14.4,35.7 12.7,35.7 12.5,35.5
+DDR_VREF on L1 "L1" (solid, remove dead copper, pour order 363): 57.9,47.9 59.7,47.9 59.7,48.5 60.3,49.1 60.4,49.2 60.9,49.2 60.9,49.7 57.9,49.7
+1V5_DDR on L1 "L1" (solid, remove dead copper, pour order 364): 57.9,50.1 59.7,50.1 59.7,52.1 58.9,52.1 58.1,51.3 57.9,51.1
GND on L1 "L1" (solid, remove dead copper, pour order 386): 13.2,69.6 18,69.6 18,64.6 13.2,64.6
GND on L1 "L1" (solid, remove dead copper, pour order 387): 23.4,72.1 24.5,72.1 24.5,70.3 24.4,70.2 23.4,70.2 23.2,70.4 23.2,70.6 23.3,70.7 23.4,70.8 23.4,72.1
GND on L1 "L1" (solid, remove dead copper, pour order 393): 2.2,40.1 2.2,38.55 0.55,38.55 0.4,38.7 0.4,39.95 0.55,40.1
+VIN_4V2 on L1 "L1" (solid, remove dead copper, pour order 394): 14.3,30.7 16.7,30.7 16.7,31.5 16,31.5 15.5,32 14.3,32
GND on L1 "L1" (solid, remove dead copper, pour order 395): 17 vertices, not listed, extent 12.1,30.9 14,33.8
GND on L1 "L1" (solid, remove dead copper, pour order 396): 16.7,33.1 16.7,32.2 14.7,32.2 14.5,32.4 14.5,33.6 14.6,33.7 14.9,33.7 16.1,33.7
GND on L1 "L1" (solid, remove dead copper, pour order 398): 18.2,32.8 18.2,31.7 18.3,31.6 18.3,29 17.5,29 17,29.5 17,29.7 17,30.9 17,32.4 17.4,32.8
+0V75_DDR_VTT on L1 "L1" (solid, remove dead copper, pour order 399): 22.5,30.2 22.5,28.9 19.9,28.9 19.8,29 18.9,29 18.9,31.4 18.8,31.5 18.8,32.8 19.6,32.8 19.7,32.8 19.7,32 19.9,31.8 19.9,30.8 20.5,30.2
GND on L1 "L1" (solid, remove dead copper, pour order 401): 18 vertices, not listed, extent 19.9,30.9 21.7,35.6
+1V375_SOC on L1 "L1" (solid, remove dead copper, pour order 402): 21.9,35.1 21.9,31.5 22.7,31.5 23,31.8 23,32 23,33 23.4,33.4 25.4,33.4 25.4,34.7 23.6,34.7 23.3,35 23.2,35.1
SW1CLX on L1 "L1" (solid, remove dead copper, pour order 403): 26,30.1 26,31.4 25.7,31.7 25.7,32.4 25.5,32.6 23.4,32.6 23.4,31.3 25,31.3 25.6,30.7 25.7,30.6 25.7,30.1
SW1LX on L1 "L1" (solid, remove dead copper, pour order 404): 27.5,30.2 26.7,30.2 26.7,32.7 27.9,32.7 27.9,31.2 27.5,30.8 27.5,30.7
+1V375_CORE on L1 "L1" (solid, remove dead copper, pour order 405): 26.7,35.4 26.8,35.5 30.1,35.5 30.1,34.7 30.3,34.5 33.3,34.5 33.3,33.8 32.55,33.8 32.3,33.55 31.85,33.1 28.7,33.1 27.9,33.9 26.7,33.9
GND on L1 "L1" (solid, remove dead copper, pour order 406): 30.8,34.7 30.8,35.5 31.1,35.5 31.5,35.9 31.8,35.9 32.2,35.5 32.2,35.1 31.8,34.7 31.5,34.7 30.8,34.7
GND on L1 "L1" (solid, remove dead copper, pour order 407): 18 vertices, not listed, extent 29.3,31.5 33.3,33.1
GND on L1 "L1" (solid, remove dead copper, pour order 408): 34.1,31.5 34.1,29.3 33.9,29.1 32.8,29.1 32.7,29.1 32.6,29.2 32.6,30.9 32.6,31 33.1,31.5
+5V on L1 "L1" (solid, remove dead copper, pour order 410): 34.7,31.5 35.4,31.5 36.1,30.8 36.8,30.8 36.8,29.1 37.1,28.8 37.2,28.7 37.2,27.1 35.9,27.1 35.9,28.3 35.7,28.5 35.5,28.7 35.1,28.7 34.7,29.1
GND on L1 "L1" (solid, remove dead copper, pour order 392): 2.2,48.05 2.2,46.5 0.55,46.5 0.4,46.65 0.4,47.9 0.55,48.05
GND on L1 "L1" (solid, remove dead copper, pour order 391): 2.2,49.9 2.2,48.35 0.55,48.35 0.4,48.5 0.4,49.75 0.55,49.9
GND on L1 "L1" (solid, remove dead copper, pour order 390): 2.2,57.85 2.2,56.3 0.55,56.3 0.4,56.45 0.4,57.7 0.55,57.85
GND on L1 "L1" (solid, remove dead copper, pour order 389): 2.2,59.7 2.2,58.15 0.55,58.15 0.4,58.3 0.4,59.55 0.55,59.7
GND on L1 "L1" (solid, remove dead copper, pour order 388): 2.2,67.65 2.2,66.1 0.55,66.1 0.4,66.25 0.4,67.5 0.55,67.65
GND on L1 "L1" (solid, remove dead copper, pour order 415): 2.2,17.4 2.2,15.6 1.9,15.3 0.8,15.3 0.8,15.4 0.7,15.5 0.7,17.2 0.9,17.4
GND on L1 "L1" (solid, remove dead copper, pour order 420): 2.2,9.4 2.2,7.3 1.9,7 0.9,7 0.8,7 0.7,7.1 0.7,9 0.7,9.2 0.9,9.4
SWBSTLX on L1 "L1" (solid, remove dead copper, pour order 423): 31.6,24.3 31.6,24.6 32.5,24.6 32.9,25 33,25.1 33,28.3 34.3,28.3 34.3,27.1 34.8,26.6 36.1,26.6 36.1,24.6 33.8,24.6 33.5,24.3
+VIN_4V2 on L1 "L1" (solid, remove dead copper, pour order 426): 21 vertices, not listed, extent 33.7,20.8 39.6,24.3
GND on L1 "L1" (solid, remove dead copper, pour order 429): 40.4,24.2 41.3,24.2 41.7,23.8 42.2,23.3 42.2,22.2 42.2,22.1 42.1,22 40.4,22 40.3,22.1 40.3,22.2 40.4,22.3 40.4,24.2
GND on L1 "L1" (solid, remove dead copper, pour order 432): 37.7,20.9 40.1,20.9 40.1,18.5 40.3,18.3 40.3,18 40.2,17.9 38.6,17.9 38.3,17.9 37.7,18.5
+VIN_5V on L1 "L1" (solid, remove dead copper, pour order 435): 36.2,18.3 36.2,17.5 36.5,17.5 37,17 37.1,16.9 37.4,16.9 37.5,17 37.5,17.1 37.5,18.8 37.4,18.9 37.3,18.9 36.8,18.9 36.2,18.3
+5V on L1 "L1" (solid, remove dead copper, pour order 438): 32.8,18.9 33,19.1 33.3,19.1 33.4,19.1 34.1,18.4 34.1,17.5 33.2,17.5 32.8,17.9 32.8,18.9
+5V_MPCIE on L1 "L1" (solid, remove dead copper, pour order 441): 31 vertices, not listed, extent 31.3,13.4 36.8,18.3
GND on L1 "L1" (solid, remove dead copper, pour order 444): 30.2,20.9 30.8,20.9 31.3,21.4 31.8,21.4 32.9,21.4 33.6,20.7 33.6,20.5 33.3,20.2 32.8,20.2 32.6,20 31.9,20 31.5,19.6 31.3,19.6 30.9,20 30.2,20
+1V5_DDR on L1 "L1" (solid, remove dead copper, pour order 448): 28.2,20.1 29.7,20.1 29.9,19.9 30,19.8 30,19.6 30.2,19.4 32.6,19.4 32.6,17 30.2,17 30.2,17.4 29.7,17.9 28.7,18.9 28.2,18.9
GND on L1 "L1" (solid, remove dead copper, pour order 451): 30.2,16.4 32.6,16.4 32.6,15.5 32.2,15.1 30.1,15.1 30,15.2 30,16.2
+VIN_4V2 on L1 "L1" (solid, remove dead copper, pour order 452): 25.9,16 25.9,12.7 28.4,12.7 28.4,14.4 29.6,15.6 29.7,15.7 29.7,17.4 29.5,17.6 29,17.6 27.4,17.6 25.9,16.1
GND on L1 "L1" (solid, remove dead copper, pour order 454): 31.3,13.4 32.3,13.4 32.8,12.9 33.3,12.9 33.3,12.3 33,12 31.6,12 31.3,12
+3V3 on L1 "L1" (solid, remove dead copper, pour order 457): 32.6,7.1 33.4,7.1 33.8,7.5 33.9,7.6 33.9,9.2 33.9,9.3 33.4,9.8 32.6,9.8 32.6,7.1
GND on L1 "L1" (solid, remove dead copper, pour order 460): 30.1,10.8 30.1,8.2 28,8.2 27.6,8.6 27.6,10.4 28,10.8
+VIN_5V on L1 "L1" (solid, remove dead copper, pour order 461): 25.2,8.2 25.2,10.8 25,10.8 21.5,14.3 21.5,16.1 21,16.1 18.7,18.4 17.8,19.3 17.2,19.3 17.2,12.5 18.3,11.4 20.3,11.4 21.4,10.3 21.4,9 22.2,8.2
+5V_USB_OTG on L1 "L1" (solid, remove dead copper, pour order 463): 28 vertices, not listed, extent 18.6,3.4 23.9,8
+5V_USB_OTG_Q on L1 "L1" (solid, remove dead copper, pour order 464): 18 vertices, not listed, extent 8.4,2.4 20.4,9
+V_INPUT on L1 "L1" (solid, remove dead copper, pour order 465): 17 vertices, not listed, extent 10.2,10.9 16.4,19.6
SW4LX on L1 "L1" (solid, remove dead copper, pour order 466): 23.6,26.6 23.6,26.3 22.9,26.3 22.6,26.6 22.4,26.8 22.1,26.8 20.4,26.8 20.4,28.1 22.6,28.1 22.6,27.2 23.1,26.7 23.2,26.6 23.6,26.6
SW2LX on L1 "L1" (solid, remove dead copper, pour order 467): 23.7,26.1 23.7,25.8 22.8,25.8 22.5,25.5 22.5,25.1 20.4,25.1 20.4,26.4 22.5,26.4 22.8,26.1
+3V3 on L1 "L1" (solid, remove dead copper, pour order 468): 18 vertices, not listed, extent 17.7,23 22.5,26.4
GND on L1 "L1" (solid, remove dead copper, pour order 469): 18 vertices, not listed, extent 18.5,27 20.2,28.9
GND on L1 "L1" (solid, remove dead copper, pour order 470): 15.7,23.3 17.1,23.3 17.2,23.3 17.2,22.8 17,22.6 16.6,22.2 16.4,22.2 16.1,22.2 15.6,22.7 15.6,23.3 15.7,23.3
GND on L1 "L1" (solid, remove dead copper, pour order 471): 20.1,23 20.3,22.8 20.3,22.5 20,22.2 19.6,21.8 18.9,21.8 18.7,21.8 18.4,22.1 17.3,22.1 17.1,22.3 17.1,22.4 17.4,22.7 17.7,23
+3V3_MCU on L1 "L1" (solid, remove dead copper, pour order 472): 22,19.4 22,17.8 22.6,17.8 22.9,18.1 23,18.2 23,19.3 22.9,19.4 22,19.4
SW3LX on L1 "L1" (solid, remove dead copper, pour order 473): 25.5,20.1 25.5,18.9 27,18.9 27,20.1 27.3,20.4 28,21.1 28,22.2 28,22.3 27.2,22.3 27.2,21.8 27,21.6 25.5,20.1
GND on L1 "L1" (solid, remove dead copper, pour order 474): 35,4 35,1.9 33.1,1.9 33.1,2 33,2.1 33,3.9 33.1,4 35,4
GND on L1 "L1" (solid, remove dead copper, pour order 475): 46.8,2.9 49,2.9 49.1,2.8 49.1,1 49,0.9 46.8,0.9
+3V3 on L1 "L1" (solid, remove dead copper, pour order 476): 53.4,15 54.3,15 54.3,14.2 54.5,14 54.9,14 55,13.9 55,13.7 55,13.6 54.8,13.4 53.9,13.4 53.4,13.9 53.4,15
GND on L1 "L1" (solid, remove dead copper, pour order 477): 49.1,20.9 51.5,20.9 51.5,18.5 50.9,17.9 49.4,17.9 49.1,18.2
+3V3_MPCIE on L1 "L1" (solid, remove dead copper, pour order 478): 98 vertices, not listed, extent 37.1,13.7 59.2,26.7
GND on L1 "L1" (solid, remove dead copper, pour order 479): 60,16.5 60,15.6 59.6,15.2 59.4,15.2 59.2,15.4 59.2,15.8 59.2,16.2 59.5,16.5 60,16.5
+1V5_DDR on L1 "L1" (solid, remove dead copper, pour order 480): 61.9,25.1 62.2,25.1 62.4,25.3 62.8,25.7 63.4,25.7 63.4,26.6 62.2,26.6 61.9,26.3 61.9,25.1
+0V75_DDR_VTT on L1 "L1" (solid, remove dead copper, pour order 481): 62.6,27.2 63.4,27.2 63.4,29 62.6,29.8 61.8,29.8 61.8,28.6 62.5,27.9 62.6,27.8 62.6,27.2
GND on L1 "L1" (solid, remove dead copper, pour order 482): 61.8,30.4 62.3,30.4 62.7,30 62.8,29.9 63,29.9 63.1,30 63.1,30.1 63.1,31.5 62.8,31.8 62.5,31.8 62.3,31.8 61.8,31.3
+VDDPU on L1 "L1" (solid, pour order 445): 39 vertices, not listed, extent 25.8,51.5 31,52.2
GND on L1 "L1" (solid, pour order 443): 39 vertices, not listed, extent 25.8,52.3 31,53
+1V375_SOC on L1 "L1" (solid, pour order 428): 47 vertices, not listed, extent 25.8,50.7 33.4,51.4
GND on L1 "L1" (solid, pour order 427): 48 vertices, not listed, extent 25.8,49.9 33.4,50.6
+1V375_CORE on L1 "L1" (solid, pour order 440): 34 vertices, not listed, extent 25.8,49.1 31.8,49.8
+1V2_VDD_ARM_CAP on L1 "L1" (solid, pour order 439): 30 vertices, not listed, extent 25.8,48 31.8,48.8
GND on L1 "L1" (solid, pour order 422): 28 vertices, not listed, extent 25.8,47.2 29.4,48.2
+1V5_DDR on L1 "L1" (solid, pour order 447): 40 vertices, not listed, extent 31,44.8 34.5,53
+1V2_VDD_ARM_CAP on L1 "L1" (solid, pour order 436): 41 vertices, not listed, extent 25.8,46.4 31.8,47.1
GND on L1 "L1" (solid, pour order 434): 26 vertices, not listed, extent 27.4,45.6 31.4,46.3
+1V375_CORE on L1 "L1" (solid, pour order 431): 41 vertices, not listed, extent 27.4,44.8 33.4,45.5
GND on L1 "L1" (solid, pour order 424): 50 vertices, not listed, extent 25.8,44 34.2,45
GND on L1 "L1" (solid, pour order 419): 22 vertices, not listed, extent 30.6,47.2 33.4,48.2
+1V1_VDDSOC_CAP on L1 "L1" (solid, pour order 413): 31.6,45.8 32.4,45.8 32.6,45.6 33,45.6 33.4,46 33.4,46.2 33.3,46.3 33.1,46.3 32.9,46.1 32.7,46.1 32.5,46.3 31.5,46.3 31.4,46.2 31.4,46
GND on L1 "L1" (solid, pour order 430): 32 vertices, not listed, extent 34.2,43.5 35.3,48.7
GND on L1 "L1" (solid, pour order 449): 37 vertices, not listed, extent 32.2,49.9 35.3,53.8
+1V1_VDDSOC_CAP on L1 "L1" (solid, pour order 416): 20 vertices, not listed, extent 32.2,48 33.4,49.8
+3V3 on L1 "L1" (solid, pour order 412): 20 vertices, not listed, extent 27.4,53.1 29.8,53.8
GND on L1 "L1" (solid, remove dead copper, pour order 483): 38.8,32 38.8,33.8 39,34 40.3,34 40.3,32.5 39.8,32 38.8,32
GND on L1 "L1" (solid, remove dead copper, pour order 484): 39.8,30.2 39.8,30.7 40.1,31 40.1,31.1 40,31.2 39.7,31.2 39.3,30.8 39.1,30.6 39.1,30.2
GND on L1 "L1" (solid, remove dead copper, pour order 485): 17 vertices, not listed, extent 42.1,29.8 43.7,34.4
+1V5_DDR on L1 "L1" (solid, remove dead copper, pour order 486): 42.2,39.1 42.2,38.2 42.9,38.2 43.1,38 43.2,37.9 43.6,37.9 44,38.3 44,38.9 43.8,39.1
+1V5_DDR on L1 "L1" (solid, remove dead copper, pour order 487): 42.2,49.3 43,49.3 43.7,50 43.7,50.4 43.4,50.7 42.7,50.7 42.2,50.2
+1V5_DDR on L1 "L1" (solid, remove dead copper, pour order 488): 42.2,63 42.2,61.9 42.6,61.5 43.2,61.5 43.7,62 43.9,62.2 43.9,62.6 43.5,63 42.2,63
+1V5_DDR on L1 "L1" (solid, remove dead copper, pour order 489): 59.7,58.3 59.7,57.4 58.4,57.4 58.3,57.5 58.3,58.4 58.4,58.5 58.8,58.5 59.5,58.5 59.7,58.3
+1V5_DDR on L1 "L1" (solid, remove dead copper, pour order 490): 59.6,46.5 59.6,45.6 58.5,45.6 58.4,45.7 58.3,45.8 58.3,46.5 58.5,46.7 59.1,46.7 59.4,46.7 59.6,46.5
GND on L1 "L1" (solid, remove dead copper, pour order 491): 59.6,45 59.6,44.1 59.4,43.9 58.4,43.9 58.3,44 58.3,45 59.6,45
GND on L1 "L1" (solid, remove dead copper, pour order 492): 59.7,52.8 59.7,53.8 59.1,54.4 58.8,54.4 58.3,53.9 58.3,53.2 58.7,52.8
GND on L1 "L1" (solid, remove dead copper, pour order 493): 58.4,56.8 60.1,56.8 60.1,56.3 59.7,55.9 58.9,55.9 58.4,56.4
GND on L1 "L1" (solid, remove dead copper, pour order 494): 42.2,63.6 43.7,63.6 43.9,63.8 44,63.9 44,65.2 43.8,65.4 43.6,65.4 43,64.8 42.9,64.7 42.7,64.7 42.4,64.7 42.2,64.5 42.2,63.6
GND on L1 "L1" (solid, remove dead copper, pour order 495): 42.2,39.7 43,39.7 43.2,39.5 43.5,39.5 43.5,40.7 43.1,41.1 42.6,41.1 42.2,40.7 42.2,39.7
+0V75_DDR_VTT on L1 "L1" (solid, remove dead copper, pour order 496): 50.7,25.1 51,25.1 51.2,24.9 51.2,24.6 51.3,24.5 51.7,24.5 51.7,23.4 50.7,23.4 50.7,23.7 50.8,23.8 50.8,24.6 50.7,24.7
+0V75_DDR_VTT on L1 "L1" (solid, remove dead copper, pour order 497): 19 vertices, not listed, extent 53,22.1 56.2,23.8
+1V5_DDR on L1 "L1" (solid, remove dead copper, pour order 498): 54.3,22.1 54.8,22.1 55.4,22.7 55.4,23.1 54.3,23.1 54.3,22.1
GND on L1 "L1" (solid, remove dead copper, pour order 499): 54.8,24 54.8,24.4 54.6,24.6 54.6,25.4 54.4,25.6 54,25.6 53.7,25.3 53.7,24
+0V75_DDR_VTT on L1 "L1" (solid, remove dead copper, pour order 500): 22 vertices, not listed, extent 57,22.8 59.3,24.7
+0V75_DDR_VTT on L1 "L1" (solid, remove dead copper, pour order 501): 61.7,22.6 61.7,23.7 61.3,24.1 59.5,24.1 59.5,23.7 60.6,23.7 60.9,23.4 60.9,22.9 61.2,22.6 61.3,22.5 61.7,22.5
+0V75_DDR_VTT on L1 "L1" (solid, remove dead copper, pour order 502): 59.4,26.7 59.4,26.8 59.1,27.1 57.9,27.1 57.9,26 58.3,26 58.5,25.8 58.6,25.7 58.6,25.3 59,25.3 59,26.4 59.2,26.6 59.3,26.6 59.4,26.7
+0V75_DDR_VTT on L1 "L1" (solid, remove dead copper, pour order 503): 23 vertices, not listed, extent 58.5,27.3 60.9,29.1
+0V75_DDR_VTT on L1 "L1" (solid, remove dead copper, pour order 504): 17 vertices, not listed, extent 58.5,29.7 60.6,31.3
+0V75_DDR_VTT on L1 "L1" (solid, remove dead copper, pour order 505): 58,32.8 59.1,32.8 59.1,33.3 59.4,33.6 59.8,33.6 59.8,34.7 59.5,34.7 59,34.2 58.7,34.2 58.7,33.8 58.5,33.6 58,33.1 58,32.8
+0V75_DDR_VTT on L1 "L1" (solid, remove dead copper, pour order 506): 61.4,25.7 61,25.7 60.8,25.9 60.3,25.9 60.3,26.3 60.6,26.6 60.6,26.9 61.7,26.9 61.9,27.1 62.1,27.1 62.2,27 62.2,26.9 61.4,26.1
GND on L1 "L1" (solid, remove dead copper, pour order 507): 65.2,66.7 66,66.7 66.3,67 66.3,68 66.3,68.2 66.6,68.5 66.6,68.7 66.5,68.8 66.4,68.8 65.8,68.8 65.4,68.4 65.1,68.1 65.1,66.8 65.2,66.7
+5V_HDR_J2 on L1 "L1" (solid, remove dead copper, pour order 508): 66.8,66.6 67.8,66.6 68.2,67 68.2,68.4 67.3,68.4 67.3,67.2 67.1,67 66.9,67 66.8,67 66.7,66.9 66.7,66.7 66.8,66.6
GND on L1 "L1" (solid, remove dead copper, pour order 509): 58.5,77.6 58.9,77.6 59.1,77.4 59.1,76.3 59,76.2 58.9,76.2 58.5,76.6
+5V_USB_TOP on L1 "L1" (solid, remove dead copper, pour order 510): 22 vertices, not listed, extent 45.2,81.1 48.8,89.1
GND on L1 "L1" (solid, remove dead copper, pour order 512): 45.4,94 48.2,94 48.6,93.6 48.6,92.3 48.2,91.9 45.4,91.9
+VIN_5V on L1 "L1" (solid, remove dead copper, pour order 513): 43.5,80.8 44,80.8 44,81.8 44.2,82 44.2,82.3 44.1,82.4 43.1,82.4 43,82.3 43,82.1 43.5,81.6
GND on L1 "L1" (solid, pour order 418): 25 vertices, not listed, extent 22.6,43.1 25,45.1
+3V3 on L8 "L8" (solid, remove dead copper, pour order 368): 23,24.6 23,24.1 22.8,23.9 19.9,23.9 18.8,25 18.8,25.6 22,25.6
+VIN_4V2 on L4 (PWR) "L10" (solid, remove dead copper, pour order 357): 22 vertices, not listed, extent 23.8,15.6 39.4,29.6
+1V5_DDR on L4 (PWR) "L4" (solid, remove dead copper, pour order 373): 45 vertices, not listed, extent 23.8,14.2 62.2,75.6
+5V_HDR_J2 on L4 (PWR) "L4" (solid, remove dead copper, pour order 374): 69,68.4 65,68.4 63.4,66.8 62.4,65.8 62.4,62.8 61.4,62.8 59.6,61 59.6,54.8 69,54.8
+3V3 on L4 (PWR) "L4" (solid, remove dead copper, pour order 375): 72 vertices, not listed, extent 1,1 69,94
+1V2_VDD_ARM_CAP on L4 (PWR) "L4" (solid, remove dead copper, pour order 376): 25,48 26.4,49.4 27,49.4 32,49.4 32.6,48.8 33.8,47.6 33.8,45.8 25,45.8
+V_INPUT on L7 (PWR) "L10" (solid, remove dead copper, pour order 362): 5.2,18.2 6.2,18.2 9.2,21.2 12.8,21.2 16.2,17.8 16.4,17.6 17.4,16.6 17.4,15.4 17.4,8 16.6,7.2 15.2,7.2 10.4,7.2 9,8.6 5.2,12.4
+VIN_4V2 on L7 (PWR) "L7" (solid, remove dead copper, pour order 385): 54 vertices, not listed, extent 1,15.2 39.6,94
+3V3_HDR on L7 (PWR) "L10" (solid, remove dead copper, pour order 348): 18.1,94 18.1,87.5 18.4,87.2 20.6,85 27.4,85 48.6,85 49.4,85.8 56.6,85.8 58.8,88 69,88 69,94
+1V5_DDR on L7 (PWR) "L4" (solid, remove dead copper, pour order 372): 51 vertices, not listed, extent 30.4,14.6 62.2,75.6
+2V5 on L7 (PWR) "L7" (solid, remove dead copper, pour order 377): 41 vertices, not listed, extent 13.8,22.2 39.6,69.4
+1V375_SOC on L7 (PWR) "L7" (solid, remove dead copper, pour order 378): 36 vertices, not listed, extent 17,32.4 36.6,61
PMIC_VDDOTP on L7 (PWR) "L7" (solid, remove dead copper, pour order 379): 18 vertices, not listed, extent 59.6,1 69,38.6
+3V3_USB_HUB on L7 (PWR) "L7" (solid, remove dead copper, pour order 380): 18 vertices, not listed, extent 57.8,39 69,81.8
+VDDA on L7 (PWR) "L7" (solid, remove dead copper, pour order 381): 51.6,15.6 52.4,15.6 53.8,14.2 60.8,14.2 62.6,12.4 62.6,10.8 62.6,9.4 61.2,9.4 60,9.4 56.8,9.4 54,6.6 53,6.6 51.6,8
+1V5_DDR on L7 (PWR) "L7" (solid, remove dead copper, pour order 383): 20 vertices, not listed, extent 1,1 35.6,42.2
+5V on L7 (PWR) "L7" (solid, remove dead copper, pour order 384): 17 vertices, not listed, extent 35.2,69.8 69,87.6
+VIN_5V on L7 (PWR) "L7" (solid, remove dead copper, pour order 382): 33 vertices, not listed, extent 17.8,1 62.6,18.8
COMP_1V375 on L10 "L10" (solid, remove dead copper, pour order 634): 17 vertices, not listed, extent 12.3,33.7 14.2,35.9
+MPCIE_SIM_VPP on L10 "L10" (solid, remove dead copper, pour order 354): 17 vertices, not listed, extent 49.5,28.3 52.4,30.5
GND on L10 "L10" (solid, remove dead copper, pour order 345): 19,46.1 19.8,46.1 19.8,46.9 20,47.1 20,47.5 19.8,47.7 19.8,48.5 20.1,48.8 20.1,49 20,49.1 19.5,49.1 18.9,48.5 18.9,46.1
GND on L10 "L10" (solid, remove dead copper, pour order 604): 35 vertices, not listed, extent 12.05,63.85 19.2,70.25
+2V5_ETH_DVDDH on L10 "L10" (solid, remove dead copper, pour order 338): 13,60.7 15.3,60.7 15.3,61.6 13,61.6
+3V3_ETH_AVDDH on L10 "L10" (solid, remove dead copper, pour order 332): 21 vertices, not listed, extent 19.9,70.7 24.45,72.3
GND on L10 "L10" (solid, remove dead copper, pour order 633): 59.6,84.5 59.6,83.6 59.4,83.4 57.8,83.4 57.7,83.5 57.7,84.4 57.8,84.5 59.6,84.5
GND on L10 "L10" (solid, remove dead copper, pour order 632): 17.5,81.3 18.1,81.3 18.4,81 18.5,81 19.2,81 19.6,81.4 19.6,82 19.5,82.1 19.4,82.1 19.2,82.1 19,81.9 18.7,81.9 17.9,81.9 17.6,81.6 17.5,81.5
+5V_MPCIE on L10 "L10" (solid, remove dead copper, pour order 631): 36.7,15.4 36.7,14 36.6,13.9 34.9,13.9 34.6,14.2 34.6,14.3 34.6,14.6 34.8,14.8 35.1,14.8 35.3,15 35.3,15.4 35.9,15.4 35.9,15 36.1,15 36.1,15.4
+1V5_MPCIE on L10 "L10" (solid, remove dead copper, pour order 630): 76 vertices, not listed, extent 31.3,18.5 57.1,26.3
+VIN_4V2 on L10 "L10" (solid, remove dead copper, pour order 629): 31.4,24.3 32.3,24.3 32.5,24.1 32.5,23.9 32.5,23.3 32,22.8 31.9,22.7 31.4,22.7
+1V2_ETH on L10 "L10" (solid, remove dead copper, pour order 628): 18 vertices, not listed, extent 17.4,71.6 19.3,73.5
+3V0_ALWAYS on L10 "L10" (solid, remove dead copper, pour order 627): 1.1,33.8 2,33.8 2.3,34.1 2.3,34.3 1.7,34.9 1.7,35.3 1.7,35.4 1.1,35.4 1.1,34.8 1.2,34.7 1.2,34.5 1.1,34.4 1.1,34.3
+VIN_5V on L10 "L10" (solid, remove dead copper, pour order 626): 67.9,67.4 68.4,66.9 68.7,66.9 68.8,67 68.8,67.9 68.8,68.7 68.7,68.8 68.3,68.8 67.9,68.4 67.9,67.4
+VIN_5V on L10 "L10" (solid, remove dead copper, pour order 622): 46.5,81.8 47.9,81.8 48,81.7 48,80.7 47.9,80.6 47.8,80.6 47.4,80.6 47.1,80.9 47,81 46.5,81
+5V_USB_TOP on L10 "L10" (solid, remove dead copper, pour order 621): 45,81.8 45.3,82.1 45.3,82.6 45.9,83.2 46.3,83.2 46.4,83.1 46.4,82.3 45.9,81.8 45.9,81 45,81
+VIN_5V on L10 "L10" (solid, remove dead copper, pour order 620): 17 vertices, not listed, extent 43,81 44.4,83.2
+5V_USB_BOT on L10 "L10" (solid, remove dead copper, pour order 619): 42,81 42,83 42.2,83.2 42.6,83.2 42.8,83 42.8,81.9 42.9,81.8 42.9,81.2 42.9,81
+5V on L10 "L10" (solid, remove dead copper, pour order 618): 18 vertices, not listed, extent 39.9,80.6 41.7,82.5
+5V_USB_OTG on L10 "L10" (solid, remove dead copper, pour order 571): 23.1,10.3 24,10.3 24,9.2 24.5,8.7 25.4,8.7 25.4,7.5 24.6,7.5 23.8,6.7 22.7,6.7 22.5,6.9 22.5,7.4 23.1,8
+NVCC_ENET on L10 "L10" (solid, remove dead copper, pour order 617): 28 vertices, not listed, extent 31.1,53.5 34.2,57.8
+3V3_USB_HUB on L10 "L10" (solid, remove dead copper, pour order 616): 18 vertices, not listed, extent 61,69.3 64.9,70.4
GND on L10 "L10" (solid, remove dead copper, pour order 615): 57.9,75.5 58.4,75.5 58.9,75 58.9,74.3 59.3,74.3 59.5,74.3 60.7,75.5 60.7,76.1 59.2,76.1 59,76.3 58.6,76.3 58.1,76.3 57.9,76.1
GND on L10 "L10" (solid, remove dead copper, pour order 614): 58.4,73.5 61.2,73.5 61.8,72.9 61.8,72 61.8,71.8 61.6,71.6 58.4,71.6
+3V3_USB_HUB on L10 "L10" (solid, remove dead copper, pour order 613): 59.1,76.5 61.3,76.5 61.4,76.6 61.4,76.8 60.9,77.3 60.6,77.6 59.8,77.6 59.6,77.6 59.2,77.2 59.1,77.1 59.1,76.5
+3V3_HDR on L10 "L10" (solid, remove dead copper, pour order 612): 60,87.4 61.3,87.4 61.5,87.6 61.8,87.9 61.8,89.9 61.6,90.1 61.5,90.1 61.2,90.1 60.9,89.8 60.7,89.6 60.7,89.5 60.7,89.3 60.5,89.1 60,88.6 60,87.4
+5V_FTDI on L10 "L10" (solid, remove dead copper, pour order 611): 37 vertices, not listed, extent 57.1,80.6 68.9,88.6
+3V3 on L10 "L10" (solid, remove dead copper, pour order 610): 55.5,88.6 55.5,87.4 53.8,87.4 53.6,87.6 53.6,87.8 53.6,88.4 53.8,88.6 55.5,88.6
+5V_USB_BOT on L10 "L10" (solid, remove dead copper, pour order 609): 45.4,89.1 45.4,87 48,87 48,87.9 48.7,88.6 48.7,89.5 48.5,89.7 48.2,89.7 47.6,89.1
GND on L10 "L10" (solid, remove dead copper, pour order 608): 34.2,73.5 34.2,71.6 35.7,71.6 35.9,71.8 36.4,72.3 36.4,73.1 36.2,73.1 36,73.3 35.4,73.9 35.2,73.9 34.6,73.9 34.2,73.5
GND on L10 "L10" (solid, remove dead copper, pour order 607): 35.5,68 36.8,68 36.8,66.6 37.3,66.1 37.3,65.3 37.3,65.2 37.1,65 35.8,65 35.5,65.3
GND on L10 "L10" (solid, remove dead copper, pour order 606): 34.3,67.9 34.3,65 34.2,64.9 34,64.9 32.9,64.9 32.6,64.9 31.8,65.7 31.6,65.9 31.6,66.4 31.6,66.6 33,68 34.3,68
+1V2_ETH_AVDDL on L10 "L10" (solid, remove dead copper, pour order 605): 17 vertices, not listed, extent 14.1,70.2 17.8,72.4
GND on L10 "L10" (solid, remove dead copper, pour order 603): 61.9,70.8 64.9,70.8 64.9,71.3 64.2,72 62.7,72 62.6,72 61.9,71.3 61.9,70.8
+5V_HDR_J2 on L10 "L10" (solid, remove dead copper, pour order 602): 21 vertices, not listed, extent 66.4,63.6 68.6,68.2
+5V on L10 "L10" (solid, remove dead copper, pour order 601): 65.8,68.2 65.8,67.4 65.1,67.4 64.5,66.8 64.4,66.7 64.2,66.7 64.1,66.8 64.1,67 63.3,67.8 63.3,68.1 63.4,68.2
GND on L10 "L10" (solid, remove dead copper, pour order 600): 59.5,68.5 60.5,68.5 61,68 61,66.3 61.4,65.9 61.5,65.8 61.5,65.5 61.3,65.3 61,65.3 59.8,65.3 59.8,67.8 59.5,68.1 59.5,68.5
GND on L10 "L10" (solid, remove dead copper, pour order 599): 57.3,68 58.4,68 58.9,67.5 59.1,67.3 59.1,66.5 59.1,65.9 58.5,65.3 57.3,65.3
GND on L10 "L10" (solid, remove dead copper, pour order 598): 62.7,47.4 62.8,47.5 64,47.5 64.1,47.4 64.1,47.3 64.1,46.3 64,46.2 63.8,46.2 63.5,46.5 62.7,46.5
+3V3_HDR on L10 "L10" (solid, remove dead copper, pour order 597): 61.1,46.5 62.3,46.5 62.5,46.7 62.5,47.6 62.4,47.7 62.3,47.7 61.4,47.7 61.1,47.4 61.1,46.5
+3V3_HDR_J2 on L10 "L10" (solid, remove dead copper, pour order 596): 19 vertices, not listed, extent 61.1,43.2 66.4,45.9
+3V3 on L10 "L10" (solid, remove dead copper, pour order 595): 61.1,44.4 61.9,44.4 62.5,43.8 62.5,43.2 62.5,43.1 62.4,43 61.2,43 61,43.2 61,44.4
GND on L10 "L10" (solid, remove dead copper, pour order 594): 57.5,42.7 59.4,42.7 59.6,42.5 59.6,41 59.6,40.9 59.4,40.7 57.5,40.7
GND on L10 "L10" (solid, remove dead copper, pour order 593): 43,42.7 44.6,42.7 46,41.3 46,40.5 45.9,40.4 45.5,40.4 45.2,40.7 44.5,40.7 42.6,40.7 42.4,40.9 42.4,42.1 43,42.7
+MPCIE_SIM_PWR on L10 "L10" (solid, remove dead copper, pour order 592): 38 vertices, not listed, extent 51.3,23.8 56.2,31.1
GND on L10 "L10" (solid, remove dead copper, pour order 591): 60.5,17.6 62.8,17.6 63.5,16.9 64.3,16.1 64.3,15 63.7,14.4 63.4,14.4 61.5,14.4 60.9,13.8 60.5,13.8 60.5,14.4
GND on L10 "L10" (solid, remove dead copper, pour order 590): 21 vertices, not listed, extent 48.6,0.9 54.4,5.6
GND on L10 "L10" (solid, remove dead copper, pour order 589): 30.3,5.6 32.9,5.6 33.4,5.1 33.4,2.1 32.7,1.4 30.3,1.4 30.3,4.3 29.7,4.9 29.7,5.3 30,5.6 30.3,5.6
+VDD_CSI on L10 "L10" (solid, remove dead copper, pour order 588): 36 vertices, not listed, extent 30,1.5 48.4,9.7
GND on L10 "L10" (solid, remove dead copper, pour order 587): 31.5,8.2 31.5,6.8 31.9,6.4 32.9,6.4 33,6.4 33.5,6.9 33.6,7 33.6,7.5 33,7.5 32.3,8.2 31.5,8.2
+3V3 on L10 "L10" (solid, remove dead copper, pour order 586): 30,8.2 30.8,8.2 31.2,7.8 31.3,7.7 31.3,6.5 31,6.2 30,6.2
GND on L10 "L10" (solid, remove dead copper, pour order 585): 33.5,17.6 33.5,13.8 32.6,12.9 31.8,12.9 30.7,14 29.9,14.8 29.9,16.4 30.8,16.4 31.2,16.8 31.2,17.6
+1V5_DDR on L10 "L10" (solid, remove dead copper, pour order 584): 31.4,18.4 31.6,18.2 31.4,18 30.6,18 30.4,18 29.9,18.5 29.8,18.6 29.8,19.4 30.7,19.4 30.7,18.6 30.9,18.4 31.4,18.4
+VIN_4V2 on L10 "L10" (solid, remove dead copper, pour order 583): 28.6,15.5 29.6,15.5 29.7,15.6 29.7,16.8 29.9,17 30.7,17 30.7,17.9 29.7,17.9 29.1,18.5 28.9,18.5 28.6,18.2 28.6,17.8
+VIN_4V2 on L10 "L10" (solid, remove dead copper, pour order 582): 23.65,24.65 23.75,24.55 24.55,24.55 24.7,24.7 24.7,24.75 24.7,25 24.75,25.05 25.15,25.45 25.35,25.45 25.35,27.05 24.45,27.05 23.65,26.25
+VIN_4V2 on L10 "L10" (solid, remove dead copper, pour order 581): 27 vertices, not listed, extent 26.55,22.05 30.1,26.15
GND on L10 "L10" (solid, remove dead copper, pour order 580): 51 vertices, not listed, extent 24.25,22.05 31.85,28.45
